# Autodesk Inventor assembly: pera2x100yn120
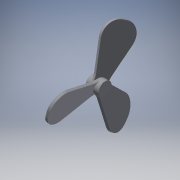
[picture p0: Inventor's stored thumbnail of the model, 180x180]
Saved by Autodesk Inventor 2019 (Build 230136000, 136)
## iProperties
Created: 2020-08
Part Number: pera2x100yn120
Material: 一般
Document SubType Name: Assembly
Designer: kikut
Author: kikut
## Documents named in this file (2)
- F:\openFOAM\bathrobo\bathrobo01\oversetmeshpera2\CAD\pera2x100yn120.iam
- F:\openFOAM\bathrobo\bathrobo01\oversetmeshpera2\CAD\pera02.ipt
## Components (1 placed, 1 different names)
1. pera02:1 — メイト:1, メイト:2
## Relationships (2: Mate 2)
- メイト:1 [Mate]: pera02:1
- メイト:2 [Mate]: pera02:1
